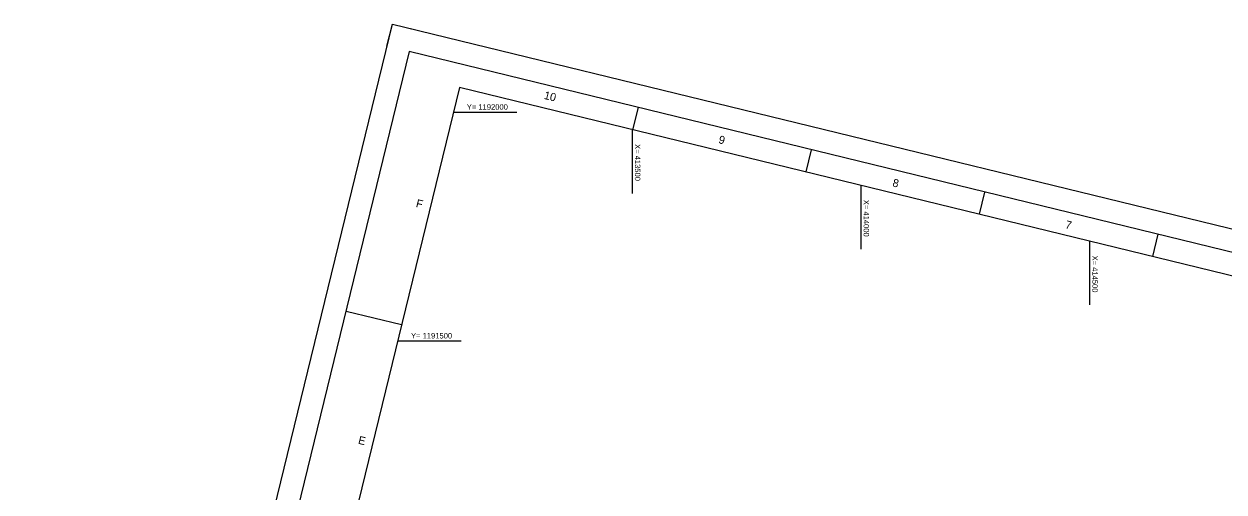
# Model space of a CAD drawing. Extents: x 412170 to 417250, y 1187847 to 1192192.
# Drawn here: x 412170 to 414793, y 1191169 to 1192192 of the extents above; entities that cross this region are included whole.
import ezdxf

# ---------------------------------------------------------------- set-up
doc = ezdxf.new("R2010")
doc.units = 0
for name, color, linetype in [('G-ANNO-NPLT', 7, 'Continuous'), ('G-ANNO-TTLB', 7, 'Continuous'), ('V-TOPO-COOR-STAT', 7, 'Continuous')]:
    doc.layers.add(name, color=color, linetype=linetype)

msp = doc.modelspace()

# ---------------------------------------------------------------- linework, layer by layer
at = {"layer": 'G-ANNO-NPLT'}
msp.add_lwpolyline([(412975.1, 1192192.3), (417249.8, 1191149.8), (416444.2, 1187846.7), (412169.5, 1188889.2)], close=True, dxfattribs=at)
msp.add_lwpolyline([(412963.2, 1192143.7), (412975.1, 1192192.3), (413023.6, 1192180.5)], dxfattribs=at)
at = {"layer": 'G-ANNO-TTLB'}
for p, q in [((413512.1, 1192009.9), (413500.3, 1191961.3)), ((413891, 1191917.5), (413879.2, 1191868.9)), ((413891, 1191917.5), (413879.2, 1191868.9)), ((414269.9, 1191825.1), (414258.1, 1191776.5)), ((414648.8, 1191732.7), (414637, 1191684.1)), ((412873.6, 1191565), (412995, 1191535.4))]:
    msp.add_line(p, q, dxfattribs=at)
for points in [[(412229.9, 1188925.9), (416407.5, 1187907.1), (417189.3, 1191113.1), (413011.8, 1192131.9)], [(417128.9, 1191076.4), (413121.4, 1192053.7), (412363.2, 1188944.8), (416370.7, 1187967.5)]]:
    msp.add_lwpolyline(points, close=True, dxfattribs=at)
at = {"layer": 'V-TOPO-COOR-STAT'}
for p, q in [((413108.3, 1192000), (413247.3, 1192000)), ((413500, 1191822.2), (413500, 1191961.1)), ((414000, 1191700.2), (414000, 1191839.2)), ((414500, 1191578.3), (414500, 1191717.3)), ((412986.4, 1191500), (413125.3, 1191500))]:
    msp.add_line(p, q, dxfattribs=at)

# ---------------------------------------------------------------- texts
at = {"layer": 'G-ANNO-TTLB'}
for s, p in [('10', (413305.3, 1192028.9)), ('9', (413687.1, 1191932.1)), ('8', (414067.3, 1191837.7)), ('F', (413025.4, 1191792.7)), ('7', (414445.1, 1191746.3)), ('E', (412899, 1191275.2))]:
    msp.add_text(s, height=17.5, rotation=346.2946, dxfattribs=at).set_placement(p)
at = {"layer": 'V-TOPO-COOR-STAT'}
for s, p in [('Y= 1192000', (413137.7, 1192005)), ('Y= 1191500', (413015.8, 1191505))]:
    msp.add_text(s, height=12, dxfattribs=at).set_placement(p)
for s, p in [('X= 413500', (413505.3, 1191929.9)), ('X= 414000', (414005.3, 1191808)), ('X= 414500', (414505.3, 1191686.1))]:
    msp.add_text(s, height=12, rotation=270, dxfattribs=at).set_placement(p)

doc.saveas('drawing.dxf')
